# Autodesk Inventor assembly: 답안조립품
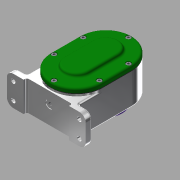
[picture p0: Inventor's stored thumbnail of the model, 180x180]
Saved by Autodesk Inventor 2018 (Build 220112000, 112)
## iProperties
Created: 2021-05
Part Number: 답안조립품
Material: 일반
Document SubType Name: Assembly
Designer: admin
Author: admin
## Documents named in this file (19)
- C:\Users\admin\Desktop\710509V1013\답안조립품.iam
- C:\Users\admin\Desktop\710509V1013\본체.ipt
- C:\Users\admin\Desktop\710509V1013\축 A.ipt
- C:\Users\admin\Desktop\710509V1013\베어링 6001.ipt
- 베어링 6001.ipt
- C:\Users\admin\Desktop\710509V1013\커버 A.ipt
- C:\Users\admin\Desktop\710509V1013\베어링 6002.ipt
- 베어링 6002.ipt
- C:\Users\admin\Desktop\710509V1013\칼라.ipt
- C:\Users\admin\Desktop\710509V1013\키 5 x 5 x 12.ipt
- C:\Users\admin\Desktop\710509V1013\스퍼기어 A.ipt
- C:\Users\admin\Desktop\710509V1013\축 B.ipt
- C:\Users\admin\Desktop\710509V1013\키 4 x 4 x 12.ipt
- C:\Users\admin\Desktop\710509V1013\스퍼기어 B.ipt
- C:\Users\admin\Desktop\710509V1013\개스킷 A.ipt
- C:\Users\admin\Desktop\710509V1013\개스킷 B.ipt
- C:\Users\admin\Desktop\710509V1013\커버 B.ipt
- C:\Users\admin\Desktop\710509V1013\볼트 M4.ipt
- C:\Users\admin\Desktop\710509V1013\오일 실 12 22 7.ipt
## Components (2 placed, 2 different names)
1. 개스킷 A:1
2. 개스킷 B:1
